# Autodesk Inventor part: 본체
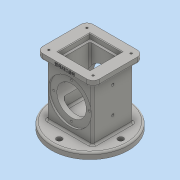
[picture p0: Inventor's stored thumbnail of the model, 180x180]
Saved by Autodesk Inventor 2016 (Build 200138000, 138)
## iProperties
Created: 2018-10
Part Number: 본체
Material: 일반
Document SubType Name: Modeling
Designer: 3sil_cad018
Density: 1 g/cm^3
Appearance: 기본값
Author: 3sil_cad018
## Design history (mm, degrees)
sketch "스케치2"
  geometry: C1 r 62.5 at (0, 0); 1 further point
  constraints: 1 centre point, 1 coincident
  dimensions: "d2" = 125 diameter of C1
extrude "돌출1" new body sketch "스케치2" distance "d3" = 10; taper "d4" = 0 deg
sketch "스케치3" dims "d5" = 100
  geometry: 3 further points
  constraints: 2 horizontal alignment, 1 coincident, 2 other
hole "구멍1" sketch "스케치3" at (50, 0) diameter "d6" = 9; stored, may be unused: countersink angle "d10" = 90 deg, drill point angle "d12" = 118 deg; dims "d7" = 6, "d8" = 4, "d9" = 2, "d11" = 8
sketch "스케치4"
  geometry: L1 (37, -33)-(-37, -33); L2 (-37, -33)-(-37, 33); L3 (-37, 33)-(37, 33); L4 (37, 33)-(37, -33); 3 further points
  constraints: 8 end point, 2 midpoint, 2 parallel, 1 horizontal, 1 horizontal alignment, 1 perpendicular, 1 vertical alignment
  dimensions: "d16" = 74 distance of L1.start L1.end; "d17" = 66 distance of L1.end L2.end
extrude "돌출2" join sketch "스케치4" distance "d18" = 88; taper "d19" = 0 deg
sketch "스케치5"
  geometry: L1 (46, -41)-(-46, -41); L2 (-46, -41)-(-46, 41); L3 (-46, 41)-(46, 41); L4 (46, 41)-(46, -41); 3 further points
  constraints: 8 end point, 2 midpoint, 2 parallel, 1 horizontal, 1 horizontal alignment, 1 perpendicular, 1 vertical alignment
  dimensions: "d20" = 92 distance of L1.start L1.end; "d21" = 82 distance of L1.end L2.end
extrude "돌출3" join sketch "스케치5" distance "d22" = 10; taper "d23" = 0 deg
sketch "스케치6"
  geometry: L1 (-26, -26)-(26, -26); L2 (26, -26)-(26, 26); L3 (26, 26)-(-26, 26); L4 (-26, 26)-(-26, -26); 3 further points
  constraints: 8 end point, 2 midpoint, 2 parallel, 1 horizontal, 1 horizontal alignment, 1 perpendicular, 1 vertical alignment
  dimensions: "d24" = 52 distance of L1.start L1.end; "d25" = 52 distance of L1.end L2.end
extrude "돌출4" cut sketch "스케치6" distance "d26" = 8; taper "d27" = 0 deg
sketch "스케치7"
  geometry: L1 (22, -22)-(-22, -22); L2 (-22, -22)-(-22, 22); L3 (-22, 22)-(22, 22); L4 (22, 22)-(22, -22); 3 further points
  constraints: 8 end point, 2 midpoint, 2 parallel, 1 horizontal, 1 horizontal alignment, 1 perpendicular, 1 vertical alignment
  dimensions: "d28" = 44 distance of L1.start L1.end; "d29" = 44 distance of L1.end L2.end
extrude "돌출5" cut sketch "스케치7" distance "d30" = 74; taper "d31" = 0 deg
fillet "모깎기1" dims "d32" = 3
fillet "모깎기2" dims "d33" = 10
fillet "모깎기3" dims "d34" = 3
fillet "모깎기4" dims "d35" = 3
sketch "스케치8"
  geometry: L1 (-28.5, -10)-(96.5, -10) reference; L2 (-2, 98)-(70, 98) reference; C1 r 35 at (34, 44); 2 further points
  constraints: 1 centre point, 1 midpoint, 1 vertical alignment
  dimensions: "d36" = 54 distance from line of L1 C1.centre; "d37" = 70 diameter of C1
extrude "돌출6" cut sketch "스케치8" distance "d38" = 3; taper "d39" = 0 deg
hole "구멍2" diameter "d42" = 48; stored, may be unused: countersink angle "d46" = 90 deg, drill point angle "d48" = 118 deg; dims "d40" = 10, "d41" = 10, "d43" = 6, "d44" = 4, "d45" = 2, "d47" = 8
sketch "스케치9" dims "d49" = 58
  geometry: A1 r 35 centre (0, 0) between (34, 8.307) and (-34, 8.307) reference; 3 further points
  constraints: 2 vertical alignment, 1 coincident, 2 other
hole "구멍3" sketch "스케치9" at (0, 29) diameter "d50" = 3.242; stored, may be unused: countersink angle "d54" = 90 deg, drill point angle "d56" = 118 deg; dims "d51" = 4, "d52" = 4, "d53" = 2, "d55" = 6
fillet "모깎기5" dims "d60" = 3
chamfer "모따기1" distance "d61" = 1; stored, may be unused: second distance "d62" = 2, angle "d63" = 45 deg
sketch "스케치10"
  geometry: A1 r 10 centre (36, -31) between (36, -41) and (46, -31) reference; A2 r 10 centre (-36, -31) between (-46, -31) and (-36, -41) reference; A3 r 10 centre (-36, 31) between (-36, 41) and (-46, 31) reference; A4 r 10 centre (36, 31) between (46, 31) and (36, 41) reference; 1 further point
  dimensions: "d64" = 72 distance of A2.centre A1.centre (derived); "d65" = 62 distance of A4.centre A1.centre (derived)
hole "구멍4" sketch "스케치10" at (36, 31), (36, -31), (-36, -31), (-36, 31) diameter "d66" = 3.242; stored, may be unused: countersink angle "d70" = 90 deg, drill point angle "d72" = 118 deg; dims "d67" = 4, "d68" = 4, "d69" = 2, "d71" = 6
sketch "스케치11"
  geometry: L1 (-32.5, -95)-(92.5, -95) reference; 4 further points
  constraints: 2 vertical alignment, 1 midpoint
  dimensions: "d73" = 37 distance from line of L1 point (30, -58); "d75" = 43 distance of point (30, -58) point (30, -15)
hole "구멍5" sketch "스케치11" at (30, -15), (30, -58) diameter "d76" = 4.134; stored, may be unused: countersink angle "d80" = 90 deg, drill point angle "d82" = 118 deg; dims "d77" = 20, "d78" = 4, "d79" = 2, "d81" = 20
fillet "모깎기6" dims "d83" = 3
sketch "스케치12"
  geometry: L1 (0, 0)-(0, 28); L2 (0, 28)-(18, 24.826); L3 (18, 24.826)-(18, 0); L4 (18, 0)-(0, 0)
  constraints: 8 end point, 1 parallel, 1 perpendicular, 1 vertical
  dimensions: "d84" = 18 distance of L3.end L1.start; "d85" = 80 deg angle of L1 L2; "d86" = 28 distance of L1.start L1.end
revolve "회전1" sketch "스케치12" stored, may be unused: angle "d87" = 90 deg
fillet "모깎기7" dims "d88" = 3
sketch "스케치13"
  geometry: L1 (82, -7)-(82, 0) reference; L2 (-10, 0)-(-10, -7) reference; L3 (0, 0)-(72, 0) reference; 2 further points
  constraints: 1 other
  dimensions: "d89" = 46 distance from line of L1 point (36, -4); "d90" = 46 distance from line of L2 point (36, -4) (derived); "d91" = 4 distance from line of L3 point (36, -4)
feature "엠보싱1" sketch "스케치13" dims "d92" = 0.5, "d93" = 0
fillet "모깎기8" dims "d94" = 3
node "솔리드1"
pattern_circular "원형 패턴1" dims angle "d14" = 360 deg
mirror "대칭1"
pattern_circular "원형 패턴2" dims angle "d58" = 360 deg
mirror "대칭2"
